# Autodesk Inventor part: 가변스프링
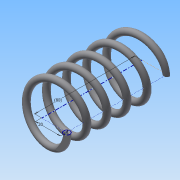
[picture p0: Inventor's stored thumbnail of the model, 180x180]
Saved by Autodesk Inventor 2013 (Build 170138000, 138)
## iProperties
Created: 2018-08
Part Number: 가변스프링
Material: 일반
Document SubType Name: Modeling
Designer: Administrator
Density: 1 g/cm^3
Mass: 12.1667 g
Surface Area: 98.6263 cm^2
Volume: 12.1667 cm^3
Author: Administrator
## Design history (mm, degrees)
sketch "스케치1"
  geometry: L1 (0, 0)-(20, 0); L2 (20, 0)-(20, 67.25); L3 (20, 67.25)-(0, 67.25); L4 (0, 67.25)-(0, 0); C1 r 2.5 at (20, 0)
  constraints: 8 end point, 2 parallel, 1 centre point, 1 coincident, 1 horizontal, 1 perpendicular
  dimensions: "d0" = 5 diameter of C1; "d1" = 67.25 distance of L3.end L1.start (derived); "d2" = 20 distance of L1.start L1.end
feature "코일1" pitch "d3" = 10; turns "d5" = 5; dims "d4" = 67.25 (= d1), "d6" = 0, angle "d7" = 90 deg, angle "d8" = 90 deg, "d9" = 0, "d10" = 0
sketch "스케치2"
  geometry: L1 (-22.5, 0)-(-17.5, 0) reference; 1 further point
  constraints: 1 horizontal alignment
extrude "돌출1" cut sketch "스케치2" distance "d11" = 10; taper "d12" = 0 deg
node "작업 평면1"
sketch "스케치3"
  geometry: L1 (22.5, 0)-(17.5, 0) reference; 1 further point
  constraints: 1 horizontal alignment
extrude "돌출2" cut sketch "스케치3" distance "d13" = 10; taper "d14" = 0 deg
node "솔리드1"
node "절단 모서리 투영1"
node "절단 모서리 투영2"
